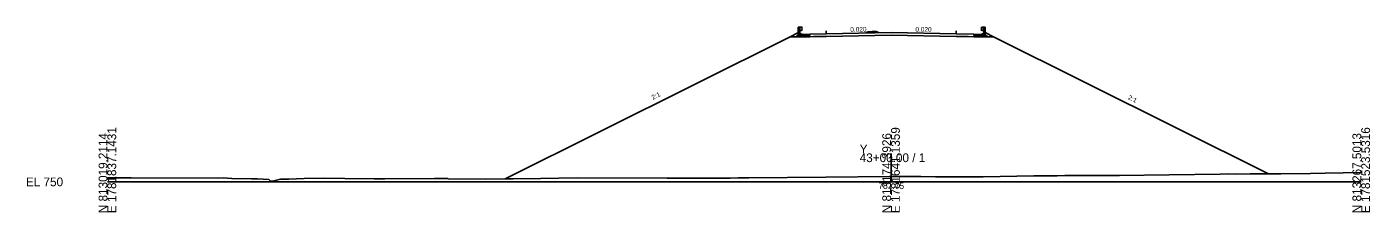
# Model space of a CAD drawing. Extents: x -12583 to 5303, y -44 to 25667.
# Drawn here: x 2874.3 to 3302.8, y 3490.3 to 3549.6 of the extents above; entities that cross this region are included whole.
import ezdxf

# ---------------------------------------------------------------- set-up
doc = ezdxf.new("R2010")
doc.units = 0
for name, color, linetype in [('Exist Cross Section Cell', 7, 'Continuous'), ('Exist XS Center Line Elevation Label', 7, 'Continuous'), ('Exist XS Ground Line', 7, 'Continuous'), ('Prop Conc 5in Monolithic Surface Mount Island', 7, 'Continuous'), ('Prop XS Dump Level', 7, 'Continuous'), ('Prop XS Earthwork Shape', 7, 'Continuous'), ('Prop XS EOT Tick Mark', 7, 'Continuous'), ('Prop XS Finish Grade', 7, 'Continuous'), ('Prop XS Finish Grade CurbGutter', 7, 'Continuous'), ('Prop XS Finish Grade Earthwork', 7, 'Continuous'), ('Prop XS Finish Grade Paved Shoulder', 7, 'Continuous'), ('Prop XS Finish Grade Pavement', 7, 'Continuous'), ('Prop XS Guardrail', 7, 'Continuous'), ('Prop XS Pvmt Edge Slope', 7, 'Continuous'), ('Prop XS SE Text', 7, 'Continuous'), ('Prop XS Side Slope Text', 7, 'Continuous'), ('Prop XS Subgrade CurbGutter', 7, 'Continuous'), ('Prop XS Subgrade Earthwork', 7, 'Continuous')]:
    doc.layers.add(name, color=color, linetype=linetype)

msp = doc.modelspace()

# ---------------------------------------------------------------- linework, layer by layer
at = {"layer": 'Exist Cross Section Cell'}
for p, q in [((3150, 3500), (3150, 3509.12)), ((2900, 3500), (3150, 3500)), ((3150, 3500), (3300, 3500))]:
    msp.add_line(p, q, dxfattribs=at)
at = {"layer": 'Exist XS Ground Line'}
for p, q in [((2900, 3501.29), (2907.57, 3501.34)), ((2907.57, 3501.34), (2935, 3501.24)), ((2935, 3501.24), (2936.93, 3501.3)), ((2936.93, 3501.3), (2939.66, 3501.11)), ((2957.83, 3500.91), (2962.75, 3501.11)), ((2962.75, 3501.11), (2969.04, 3501.22)), ((2969.04, 3501.22), (2975.7, 3501.06)), ((3004.38, 3501.09), (3008.65, 3501.12)), ((3008.65, 3501.12), (3008.75, 3501.01)), ((3038.14, 3501.07), (3049.85, 3501.29)), ((3049.85, 3501.29), (3078.61, 3501.14)), ((3078.61, 3501.14), (3098.66, 3501.24)), ((3098.66, 3501.24), (3101.18, 3501.28)), ((3101.18, 3501.28), (3104.67, 3501.29)), ((3104.67, 3501.29), (3129.22, 3501.52)), ((3129.22, 3501.52), (3149.5, 3501.75)), ((3149.5, 3501.75), (3150, 3501.75)), ((3150, 3501.75), (3159.5, 3501.73)), ((3159.5, 3501.73), (3164.16, 3501.6)), ((3164.16, 3501.6), (3165.41, 3501.62)), ((3165.41, 3501.62), (3177.52, 3501.65)), ((3177.52, 3501.65), (3179.37, 3501.59)), ((3179.37, 3501.59), (3195.55, 3501.91)), ((3195.55, 3501.91), (3202.95, 3501.98)), ((3202.95, 3501.98), (3205.41, 3502.04)), ((3205.41, 3502.04), (3206.65, 3502.08)), ((3206.65, 3502.08), (3212.63, 3502.08)), ((3212.63, 3502.08), (3218.99, 3502.08)), ((3218.99, 3502.08), (3222.85, 3502.03)), ((3222.85, 3502.03), (3238.71, 3502.24)), ((3238.71, 3502.24), (3255, 3502.46)), ((3255, 3502.46), (3257.73, 3502.53)), ((3257.73, 3502.53), (3259.91, 3502.51)), ((3259.91, 3502.51), (3264.56, 3502.57)), ((3264.56, 3502.57), (3273.6, 3502.55)), ((3273.6, 3502.55), (3274.37, 3502.55)), ((3274.37, 3502.55), (3283.85, 3502.63)), ((3283.85, 3502.63), (3288.48, 3502.76)), ((3288.48, 3502.76), (3300, 3503.04)), ((2939.66, 3501.11), (2945.92, 3500.96)), ((2945.92, 3500.96), (2947.86, 3501)), ((2947.86, 3501), (2951.46, 3500.74)), ((2951.46, 3500.74), (2951.96, 3500.3)), ((2951.96, 3500.3), (2952.65, 3500.2)), ((2952.65, 3500.2), (2954.8, 3500.75)), ((2954.8, 3500.75), (2955.26, 3500.88)), ((2955.26, 3500.88), (2957.83, 3500.91)), ((2975.7, 3501.06), (2985.06, 3500.94)), ((2985.06, 3500.94), (2986.94, 3500.97)), ((2986.94, 3500.97), (2988.56, 3500.96)), ((2988.56, 3500.96), (3004.38, 3501.09)), ((3008.75, 3501.01), (3020.72, 3500.88)), ((3020.72, 3500.88), (3038.14, 3501.07))]:
    msp.add_line(p, q, dxfattribs=at)
at = {"layer": 'Prop Conc 5in Monolithic Surface Mount Island'}
for p, q in [((3142, 3547.73), (3142.74, 3548)), ((3142, 3547.56), (3142, 3547.73)), ((3142.74, 3548), (3143.99, 3548.05)), ((3145.24, 3548.05), (3143.99, 3548.05)), ((3146, 3547.81), (3145.24, 3548.05)), ((3146, 3547.64), (3146, 3547.81))]:
    msp.add_line(p, q, dxfattribs=at)
at = {"layer": 'Prop XS Dump Level'}
for p, q in [((3129.25, 3547.31), (3150, 3547.72)), ((3150, 3547.72), (3170.75, 3547.31))]:
    msp.add_line(p, q, dxfattribs=at)
at = {"layer": 'Prop XS Earthwork Shape'}
msp.add_lwpolyline([(3255, 3502.46), (3257.73, 3502.53), (3259.91, 3502.51), (3264.56, 3502.57), (3270.37, 3502.56), (3182.68, 3546.4), (3180.81, 3546.4), (3176.42, 3546.4), (3174.75, 3546.44), (3170.75, 3546.52), (3150, 3546.93), (3129.25, 3546.52), (3125.25, 3546.44), (3124.05, 3546.41), (3119.66, 3546.41), (3117.78, 3546.41), (3026.86, 3500.95), (3038.14, 3501.07), (3049.85, 3501.29), (3078.61, 3501.14), (3098.66, 3501.24), (3101.18, 3501.28), (3104.67, 3501.29), (3129.22, 3501.52), (3149.5, 3501.75), (3150, 3501.75), (3159.5, 3501.73), (3164.16, 3501.6), (3165.41, 3501.62), (3177.52, 3501.65), (3179.37, 3501.59), (3195.55, 3501.91), (3202.95, 3501.98), (3205.41, 3502.04), (3206.65, 3502.08), (3212.63, 3502.08), (3218.99, 3502.08), (3222.85, 3502.03), (3238.71, 3502.24)], close=True, dxfattribs=at)
at = {"layer": 'Prop XS EOT Tick Mark'}
for p, q in [((3129.25, 3547.31), (3129.25, 3548.31)), ((3170.75, 3547.31), (3170.75, 3548.31))]:
    msp.add_line(p, q, dxfattribs=at)
at = {"layer": 'Prop XS Finish Grade'}
for p, q in [((3120.45, 3547.74), (3117.78, 3546.41)), ((3121.03, 3547.45), (3120.45, 3547.74)), ((3179.44, 3547.44), (3180.02, 3547.73)), ((3182.68, 3546.4), (3180.02, 3547.73))]:
    msp.add_line(p, q, dxfattribs=at)
at = {"layer": 'Prop XS Finish Grade CurbGutter'}
for p, q in [((3121.72, 3547.11), (3121.03, 3547.45)), ((3124.05, 3547.21), (3121.72, 3547.11)), ((3176.42, 3547.2), (3178.75, 3547.1)), ((3178.75, 3547.1), (3179.44, 3547.44))]:
    msp.add_line(p, q, dxfattribs=at)
at = {"layer": 'Prop XS Finish Grade Earthwork'}
for p, q in [((3117.78, 3546.41), (3026.86, 3500.95)), ((3182.68, 3546.4), (3270.37, 3502.56))]:
    msp.add_line(p, q, dxfattribs=at)
at = {"layer": 'Prop XS Finish Grade Paved Shoulder'}
for p, q in [((3129.25, 3547.31), (3124.05, 3547.21)), ((3170.75, 3547.31), (3176.42, 3547.2))]:
    msp.add_line(p, q, dxfattribs=at)
at = {"layer": 'Prop XS Finish Grade Pavement'}
for p, q in [((3129.25, 3547.31), (3150, 3547.72)), ((3150, 3547.72), (3170.75, 3547.31)), ((3150, 3547.72), (3170.75, 3547.31))]:
    msp.add_line(p, q, dxfattribs=at)
at = {"layer": 'Prop XS Guardrail'}
for p, q in [((3120.4, 3549.51), (3120.9, 3549.51)), ((3120.4, 3547.01), (3120.4, 3549.51)), ((3120.9, 3549.51), (3121.4, 3549.51)), ((3120.9, 3549.51), (3120.9, 3547.01)), ((3121.4, 3548.37), (3120.9, 3548.37)), ((3121.4, 3549.51), (3121.69, 3549.31)), ((3121.69, 3549.19), (3121.4, 3548.99)), ((3121.4, 3548.99), (3121.4, 3548.89)), ((3121.4, 3548.89), (3121.69, 3548.69)), ((3121.69, 3548.57), (3121.4, 3548.37)), ((3121.69, 3549.31), (3121.72, 3549.25)), ((3121.72, 3549.25), (3121.69, 3549.19)), ((3121.69, 3548.69), (3121.72, 3548.63)), ((3121.72, 3548.63), (3121.69, 3548.57)), ((3178.78, 3549.3), (3178.75, 3549.24)), ((3178.75, 3549.24), (3178.78, 3549.18)), ((3178.78, 3548.68), (3178.75, 3548.62)), ((3178.75, 3548.62), (3178.78, 3548.56)), ((3179.07, 3549.5), (3178.78, 3549.3)), ((3178.78, 3549.18), (3179.07, 3548.98)), ((3179.07, 3548.88), (3178.78, 3548.68)), ((3178.78, 3548.56), (3179.07, 3548.36)), ((3179.57, 3549.5), (3179.07, 3549.5)), ((3179.07, 3548.98), (3179.07, 3548.88)), ((3179.07, 3548.36), (3179.57, 3548.36)), ((3180.07, 3549.5), (3179.57, 3549.5)), ((3179.57, 3549.5), (3179.57, 3547)), ((3180.07, 3547), (3180.07, 3549.5))]:
    msp.add_line(p, q, dxfattribs=at)
at = {"layer": 'Prop XS Pvmt Edge Slope'}
for p, q in [((3120.03, 3546.79), (3119.66, 3546.41)), ((3121.03, 3546.79), (3120.03, 3546.79)), ((3179.44, 3546.78), (3180.44, 3546.78)), ((3180.44, 3546.78), (3180.81, 3546.4))]:
    msp.add_line(p, q, dxfattribs=at)
at = {"layer": 'Prop XS Subgrade CurbGutter'}
for p, q in [((3121.03, 3546.79), (3121.03, 3547.45)), ((3124.05, 3546.79), (3121.03, 3546.79)), ((3124.05, 3547.21), (3124.05, 3546.79)), ((3176.42, 3547.2), (3176.42, 3546.78)), ((3176.42, 3546.78), (3179.44, 3546.78)), ((3179.44, 3546.78), (3179.44, 3547.44))]:
    msp.add_line(p, q, dxfattribs=at)
at = {"layer": 'Prop XS Subgrade Earthwork'}
for p, q in [((3119.66, 3546.41), (3117.78, 3546.41)), ((3124.05, 3546.41), (3119.66, 3546.41)), ((3125.25, 3546.44), (3124.05, 3546.41)), ((3129.25, 3546.52), (3125.25, 3546.44)), ((3150, 3546.93), (3129.25, 3546.52)), ((3170.75, 3546.52), (3150, 3546.93)), ((3170.75, 3546.52), (3174.75, 3546.44)), ((3174.75, 3546.44), (3176.42, 3546.4)), ((3176.42, 3546.4), (3176.42, 3546.4)), ((3176.42, 3546.4), (3180.81, 3546.4)), ((3180.81, 3546.4), (3182.68, 3546.4))]:
    msp.add_line(p, q, dxfattribs=at)

# ---------------------------------------------------------------- texts
at = {"layer": 'Exist Cross Section Cell'}
for s, p in [('N 813019.2114', (2900, 3490)), ('E 1781837.1431', (2902.8, 3490)), ('N 813174.3926', (3150, 3490)), ('E 1781641.1359', (3152.8, 3490)), ('N 813267.5013', (3300, 3490)), ('E 1781523.5316', (3302.8, 3490))]:
    msp.add_text(s, height=2.8, rotation=90, dxfattribs=at).set_placement(p)
for s, p in [('Y', (3140, 3509.12)), ('43+00.00 / 1', (3140, 3506.32)), ('EL 750', (2874, 3498.6))]:
    msp.add_text(s, height=2.8, dxfattribs=at).set_placement(p)
at = {"layer": 'Exist XS Center Line Elevation Label'}
msp.add_text('751.75', height=2, dxfattribs=at).set_placement((3145.98, 3497.75))
at = {"layer": 'Prop XS Dump Level'}
msp.add_text('Case2', height=0.04, dxfattribs=at).set_placement((3176.42, 3547.16))
at = {"layer": 'Prop XS SE Text'}
for rotation, p in [(1.1458, (3137, 3547.96)), (358.8542, (3157.75, 3548.07)), (358.8542, (3157.75, 3548.07))]:
    msp.add_text('0.020', height=1.5, rotation=rotation, dxfattribs=at).set_placement(p)
at = {"layer": 'Prop XS Side Slope Text'}
for rotation, p in [(26.5651, (3074.05, 3526.22)), (333.4349, (3225.44, 3526.5))]:
    msp.add_text('2:1', height=1.5, rotation=rotation, dxfattribs=at).set_placement(p)

doc.saveas('drawing.dxf')
